// Mitsubishi GX Works2 project: MC-29MR-14MTS-F500-H3G-B   PLC: FX3G

PROGRAM MAIN
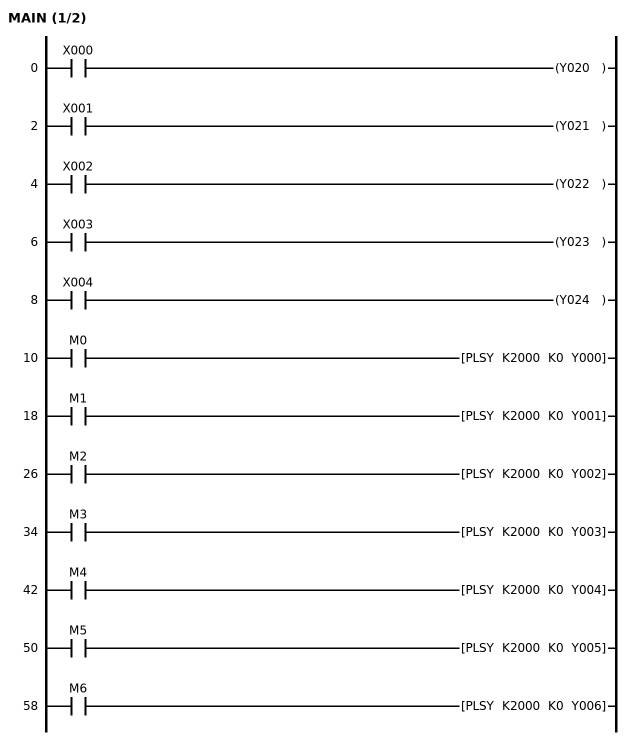
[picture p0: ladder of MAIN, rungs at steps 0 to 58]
0     LD      X000
      OUT     Y020
2     LD      X001
      OUT     Y021
4     LD      X002
      OUT     Y022
6     LD      X003
      OUT     Y023
8     LD      X004
      OUT     Y024
10    LD      M0
      PLSY    K2000 K0 Y000
18    LD      M1
      PLSY    K2000 K0 Y001
26    LD      M2
      PLSY    K2000 K0 Y002
34    LD      M3
      PLSY    K2000 K0 Y003
42    LD      M4
      PLSY    K2000 K0 Y004
50    LD      M5
      PLSY    K2000 K0 Y005
58    LD      M6
      PLSY    K2000 K0 Y006
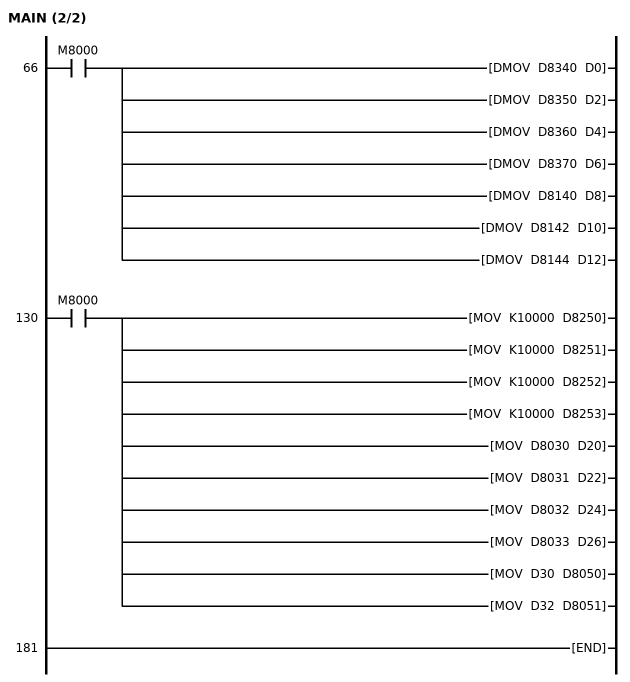
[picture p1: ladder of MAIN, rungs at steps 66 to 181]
66    LD      M8000
      DMOV    D8340 D0
      DMOV    D8350 D2
      DMOV    D8360 D4
      DMOV    D8370 D6
      DMOV    D8140 D8
      DMOV    D8142 D10
      DMOV    D8144 D12
130   LD      M8000
      MOV     K10000 D8250
      MOV     K10000 D8251
      MOV     K10000 D8252
      MOV     K10000 D8253
      MOV     D8030 D20
      MOV     D8031 D22
      MOV     D8032 D24
      MOV     D8033 D26
      MOV     D30 D8050
      MOV     D32 D8051
181   END
END_PROGRAM
